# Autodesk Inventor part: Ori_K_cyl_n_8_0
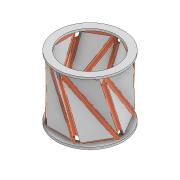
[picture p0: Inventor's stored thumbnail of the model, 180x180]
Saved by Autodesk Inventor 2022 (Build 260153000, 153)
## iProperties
Created: 2022-08
Part Number: Ori_K_cyl_n_8_0
Material: Generic
Document SubType Name: Modeling
Designer: Samy
Density: 1 g/cm^3
Appearance: Default
d234: 360.00 deg
Author: Samy
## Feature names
1. Rectangular Pattern1
2. Split2
3. Split3
4. Extrusion1
5. Rectangular Pattern2
6. Split4
7. Split5
8. Split6
9. Split7
10. Split8
11. Split9
12. Split10
13. Split11
14. Sweep8
15. Sweep9
16. Sweep10
17. Sweep11
18. Sweep12
19. Circular Pattern6
20. Circular Pattern7
21. Circular Pattern8
22. Circular Pattern9
23. Split12 to MEASURE VALLEYS
## Parameters: th = 0.75 mm, th_h = 1.5 mm, d3 = 1.5 mm, d4 = 1.5 mm, d5 = 1.5 mm, Hc = 17.5 mm, d21 = 0.75 mm, d22 = 1.5 mm, d23 = 1.5 mm, d24 = 1.5 mm, d25 = 1.5 mm, d36 = 0, d37 = 0, d38 = 5 mm, d39 = 0, d40 = 0, d41 = 0, d42 = 0, d43 = 0, d44 = 0, d45 = 5 mm, d46 = 5 mm, d47 = 0, d48 = 5 mm, d49 = 5 mm, d50 = 0, d51 = 0, d52 = 0, d53 = 0, d54 = 0, d57 = 0, d58 = 0, d59 = 5 mm, d60 = 0, d61 = 5 mm, d62 = 0, d65 = 0, d66 = 5 mm, d67 = 5 mm, d68 = 0, d69 = 5 mm, d70 = 0, d71 = 0, d72 = 0, d73 = 0, d74 = 0, d75 = 0, d76 = 0, d77 = 0, d78 = 0, d79 = 0, th_v = 0.67416 mm, d84 = 0.67416 mm, d85 = 0.67416 mm, d86 = 0.67416 mm, d87 = 0, d88 = 0, d89 = 5 mm, d90 = 0, d91 = 5 mm, d92 = 5 mm, d93 = 5 mm, d94 = 0, d95 = 5 mm, d96 = 0, d97 = 5 mm, d98 = 5 mm, d99 = 5 mm, d100 = 0, d101 = 0, d102 = 5 mm, d103 = 5 mm, d104 = 0, d105 = 5 mm, d106 = 5 mm, d107 = 5 mm, d108 = 0, d118 = 0, d123 = 5 mm, d124 = 0, d125 = 5 mm, d126 = 0, d127 = 5 mm, d128 = 0, d129 = 5 mm, d130 = 5 mm, d131 = 5 mm, d132 = 0, d133 = 0, d134 = 0, d135 = 0, d136 = 5 mm, d137 = 5 mm, d138 = 0, d141 = 0, d142 = -0.67416 mm, d143 = 0.67416 mm, Hsol = 0.625 mm, d145 = 0, d148 = 18.125 mm, d159 = 17.5 mm, th_h_d = 1.2 mm, c_p = -1.5 mm, d177 = 1.5 mm, d197 = 1.2 mm, d198 = 1.2 mm, d199 = 1.2 mm, d200 = 1.2 mm, th_h_d_v = 0.84 mm, d202 = 1.2 mm, d203 = 1.2 mm, d204 = 0, d205 = 0, d206 = 1.2 mm, d207 = 0, d208 = 0, d209 = 0, d210 = 0, d211 = 0, d212 = 0, d213 = 0, d214 = 0, d216 = 360 deg, d219 = 360 deg, d222 = 360 deg, d234 = 360 deg, d_T_v = 0.42 mm, d_cut_p = 1.03968 mm, r_d = 11.54207 mm, d_L_v = 0.44107 mm
